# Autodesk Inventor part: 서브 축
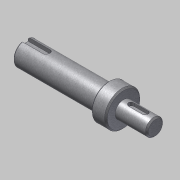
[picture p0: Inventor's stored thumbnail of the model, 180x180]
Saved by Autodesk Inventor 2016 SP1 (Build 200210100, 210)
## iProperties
Created: 2016-04
Part Number: 서브 축
Document SubType Name: Modeling
Designer: mdu
Density: 1 g/cm^3
Mass: 19.9624 g
Surface Area: 57.7178 cm^2
Volume: 19.9624 cm^3
Material: 강철, 연강
Appearance: 금속-강(스테인리스, 브러시됨)
Author: mdu
Revision Number: 1
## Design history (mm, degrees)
sketch "스케치1"
  geometry: L1 (-16.331, 0)-(-108.831, 0); L2 (-16.331, 0)-(-16.331, -6); L3 (-16.331, -6)-(-38.831, -6); L4 (-38.831, -12.5)-(-46.5, -12.5); L5 (-46.5, -8.5)-(-108.831, -8.5); L6 (-108.831, -8.5)-(-108.831, 0); L7 (-46.5, -8.5)-(-46.5, -12.5); L8 (-38.831, -6)-(-38.831, -12.5); L9 (-46.5, 12.249)-(-46.5, -12.249) reference; L10 (-38.831, -17)-(-38.831, 17) reference; 2 further points
  constraints: 17 end point, 4 perpendicular, 2 collinear, 2 parallel, 1 horizontal, 1 midpoint, 1 point on line
  dimensions: "d1" = 12 diameter of L3 L1; "d2" = 25 diameter of L4 L1; "d3" = 17 diameter of L5 L1; "d18" = 22.5 distance of L2.end L3.end; "d20" = 70 distance between parallel lines of L6 L8; "d21" = 7.66872 distance of L4.start L4.end (derived)
revolve "회전1" sketch "스케치1" stored, may be unused: angle "d5" = 90 deg
chamfer "모따기1" distance "d6" = 1; stored, may be unused: second distance "d7" = 2, angle "d8" = 45 deg
node "작업 평면1"
sketch "스케치2"
  geometry: L1 (11.25, 5)-(11.25, -5) reference; L2 (-5.75, -2)-(4.25, -2); L3 (4.25, 2)-(-5.75, 2); A1 r 2 centre (4.25, 0) between (4.25, -2) and (4.25, 2); A2 r 2 centre (-5.75, 0) between (-5.75, 2) and (-5.75, -2); 2 further points
  constraints: 4 end point, 4 point on circle, 4 tangent, 2 centre point, 1 horizontal alignment, 1 midpoint, 1 parallel, 1 perpendicular
  dimensions: "d9" = 4 distance between parallel lines of L2 L3; "d10" = 14 dimension on A1 A2; "d11" = 5 distance edge to line of A1 L1
extrude "돌출1" cut sketch "스케치2" distance "d12" = 2.5; taper "d13" = 0 deg
node "작업 평면2"
sketch "스케치3"
  geometry: L1 (-31.166, -7.5)-(-31.166, 7.5) reference; L2 (-31.166, 2.5)-(-15.666, 2.5); L3 (-15.666, -2.5)-(-31.166, -2.5); A1 r 2.5 centre (-15.666, 0) between (-15.666, -2.5) and (-15.666, 2.5); 2 further points
  constraints: 4 end point, 2 perpendicular, 2 point on circle, 2 point on line, 2 tangent, 1 centre point, 1 horizontal alignment, 1 midpoint
  dimensions: "d14" = 5 distance between parallel lines of L3 L2; "d15" = 18 dimension on A1 L1
extrude "돌출2" cut sketch "스케치3" distance "d16" = 3; taper "d17" = 0 deg
sketch "스케치4"
  geometry: C1 r 12.5 at (0, 0) reference; 1 further point
extrude "돌출3" join sketch "스케치4" distance "d22" = 3; taper "d23" = 0 deg
chamfer "모따기2" distance "d24" = 1; stored, may be unused: second distance "d25" = 2, angle "d26" = 45 deg
node "솔리드1"
node "참조4"
node "참조5"
